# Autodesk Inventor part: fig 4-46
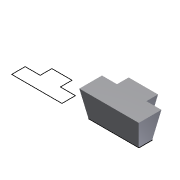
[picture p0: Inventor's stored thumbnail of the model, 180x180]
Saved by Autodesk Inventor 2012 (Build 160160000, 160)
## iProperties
Created: 2004-05
Part Number: fig 4-46
Document SubType Name: Modeling
Designer: CADCIM Technologies
Manufacturer: Standard
Standards Organization: Custom
Density: 1 g/cm^3
Material: Default
Author: CADCIM Technologies
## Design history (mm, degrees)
sketch "Sketch1"
  geometry: L1 (31.783, 34.561)-(31.783, 22.933); L2 (31.783, 22.933)-(16.796, 22.933); L3 (16.796, 22.933)-(16.796, 9.496); L4 (16.796, 9.496)-(66.925, 9.496); L5 (66.925, 9.496)-(66.925, 22.933); L6 (66.925, 22.933)-(51.938, 22.933); L7 (51.938, 22.933)-(51.938, 34.561); L8 (51.938, 34.561)-(31.783, 34.561); L9 (-45.013, 34.561)-(-45.013, 22.933); L10 (-45.013, 22.933)-(-60, 22.933); L11 (-60, 22.933)-(-60, 9.496); L12 (-60, 9.496)-(-9.871, 9.496); L13 (-9.871, 9.496)-(-9.871, 22.933); L14 (-9.871, 22.933)-(-24.858, 22.933); L15 (-24.858, 22.933)-(-24.858, 34.561); L16 (-24.858, 34.561)-(-45.013, 34.561)
  constraints: 32 end point, 10 parallel, 4 equal length, 2 collinear, 2 perpendicular, 2 vertical
extrude "Extrusion2" new body sketch "Sketch1" distance "d2" = 26; taper "d3" = 10 deg
body "Solid2"
